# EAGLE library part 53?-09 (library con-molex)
CONNECTOR wire to board 1.25 mm (.049 inch) pitch header
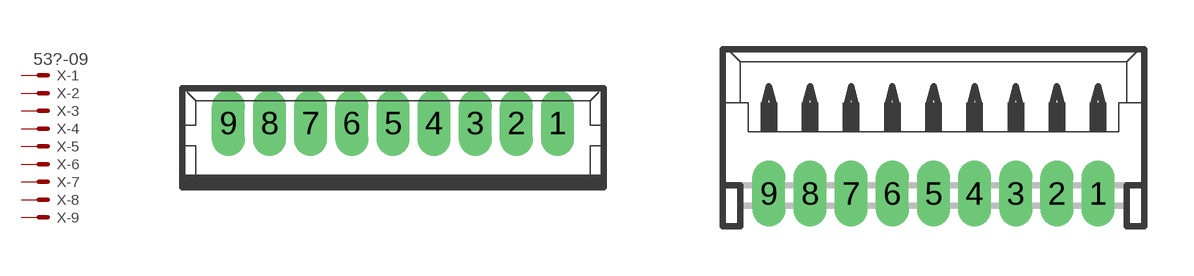
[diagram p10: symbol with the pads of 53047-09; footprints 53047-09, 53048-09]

Designator prefix X; gates -1=MV -2=M -3=M -4=M -5=M -6=M -7=M -8=M -9=M

## 53047-09 (MPN: 53047-0910; OC_FARNELL: 9732888; OC_NEWARK: 98K9827)  [53047-09]
1  -1:S  pas
2  -2:S  pas
3  -3:S  pas
4  -4:S  pas
5  -5:S  pas
6  -6:S  pas
7  -7:S  pas
8  -8:S  pas
9  -9:S  pas

## 53048-09 (MPN: 53048-0910; OC_FARNELL: 1012239; OC_NEWARK: 98K9837)  [53048-09]
Pads as for 53047-09

## 53261-09 (MPN: 53261-0971; OC_FARNELL: 1125362; OC_NEWARK: 93K4249)  [53261-09]
Pads as for 53047-09

## 53398-09 (OC_FARNELL: unknown; OC_NEWARK: unknown)  [53398-09]
Pads as for 53047-09

## Footprint 53047-09 (pad centres in mm)
CONNECTOR wire to board 1.25 mm (.049 inch) pitch header straight Sourcxe: http://www.molex.com/pdm_docs/sd/530470210_sd.pdf
drill 0.5 pad 0.698 long: 1 5,0.45; 2 3.75,0.45; 3 2.5,0.45; 4 1.25,0.45; 5 0,0.45; 6 -1.25,0.45; 7 -2.5,0.45; 8 -3.75,0.45; 9 -5,0.45

## Footprint 53048-09 (pad centres in mm)
CONNECTOR wire to board 1.25 mm (.049 inch) pitch header right angle
drill 0.5 pad 0.698 long: 1 5,-1.25; 2 3.75,-1.25; 3 2.5,-1.25; 4 1.25,-1.25; 5 0,-1.25; 6 -1.25,-1.25; 7 -2.5,-1.25; 8 -3.75,-1.25; 9 -5,-1.25

## Footprint 53261-09 (pad centres in mm)
CONNECTOR wire to board 1.25 mm (.049 inch) pitch header SMT right angle
smd 0.8 x 2: 1 5,-2.5; 2 3.75,-2.5; 3 2.5,-2.5; 4 1.25,-2.5; 5 0,-2.5; 6 -1.25,-2.5; 7 -2.5,-2.5; 8 -3.75,-2.5; 9 -5,-2.5
smd 2.1 x 3: S1 7.5,0.625; S2 -7.5,0.625

## Footprint 53398-09 (pad centres in mm)
CONNECTOR wire to board 1.25 mm (.049 inch) pitch header SMT straight
smd 0.8 x 1.8: 1 5,-2.5; 2 3.75,-2.5; 3 2.5,-2.5; 4 1.25,-2.5; 5 0,-2.5; 6 -1.25,-2.5; 7 -2.5,-2.5; 8 -3.75,-2.5; 9 -5,-2.5
smd 2.1 x 3: S1 7.5,0.625; S2 -7.5,0.625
